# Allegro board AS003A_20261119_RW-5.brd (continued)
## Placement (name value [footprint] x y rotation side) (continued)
NOREF#208  -  []  327.06 232.39 0 top
NOREF#209  -  []  289.38 211.71 90 top
NOREF#210  -  []  355.47 246.3 90 top
NOREF#211  -  []  282.75 189.55 0 top
NOREF#212  -  []  266.93 277.4 90 top
NOREF#213  -  []  295.78 216.51 0 top
NOREF#214  -  []  296.03 211.93 90 top
NOREF#215  -  []  288.58 217.31 90 top
NOREF#216  -  []  295.78 214.91 90 top
NOREF#217  -  []  254.59 208.91 0 top
NOREF#218  -  []  298.43 215.93 90 top
NOREF#219  -  []  312.79 276.59 0 top
NOREF#220  -  []  298.13 277.21 0 top
NOREF#221  -  []  73.08 198.04 90 top
NOREF#222  -  []  282.98 208.51 0 top
NOREF#223  -  []  238.25 277.7 90 top
NOREF#224  -  []  313.37 277.4 90 top
NOREF#225  -  []  306.49 215.7 90 top
NOREF#226  -  []  290.98 214.91 0 top
NOREF#227  -  []  343.76 238.65 0 top
NOREF#228  -  []  296.58 218.91 90 top
NOREF#229  -  []  292.33 247.22 0 top
NOREF#230  -  []  328.93 276.31 90 top
NOREF#231  -  []  293.38 217.31 90 top
NOREF#232  -  []  39.3 175.77 0 top
NOREF#233  -  []  288.58 214.11 0 top
NOREF#234  -  []  281.85 277.7 90 top
NOREF#235  -  []  297.85 277.7 0 top
NOREF#236  -  []  289.38 218.11 0 top
NOREF#237  -  []  296.83 217.53 90 top
NOREF#238  -  []  292.58 208.51 0 top
NOREF#239  -  []  253.82 277.4 90 top
NOREF#240  -  []  293.38 209.31 0 top
NOREF#241  -  []  292.35 251.77 0 top
NOREF#242  -  []  275.17 219.77 90 top
NOREF#243  -  []  282.17 277.4 90 top
NOREF#244  -  []  56.28 217.19 90 top
NOREF#245  -  []  292.03 211.13 90 top
NOREF#246  -  []  283.78 207.71 0 top
NOREF#247  -  []  288.58 217.31 0 top
NOREF#248  -  []  284.83 210.33 90 top
NOREF#249  -  []  292.58 213.31 90 top
NOREF#250  -  []  306.49 212.15 90 top
NOREF#251  -  []  343.22 225.85 0 top
NOREF#252  -  []  280.08 250.87 0 top
NOREF#253  -  []  54.49 178.75 90 top
NOREF#254  -  []  268.41 276.01 0 top
NOREF#255  -  []  364.36 226.82 90 top
NOREF#256  -  []  297.63 210.33 90 top
NOREF#257  -  []  55.48 174.78 90 top
NOREF#258  -  []  284.3 277.4 90 top
NOREF#259  -  []  286.98 209.31 0 top
NOREF#260  -  []  297.63 213.53 90 top
NOREF#261  -  []  297.57 177.1 90 top
NOREF#262  -  []  166.64 181.61 0 top
NOREF#263  -  []  293.63 207.93 90 top
NOREF#264  -  []  54.49 203.06 0 top
NOREF#265  -  []  56 218.47 0 top
NOREF#266  -  []  44.57 154.4 0 top
NOREF#267  -  []  286.18 208.51 0 top
NOREF#268  -  []  354.12 225.85 90 top
NOREF#269  -  []  284.58 213.31 90 top
NOREF#270  -  []  355.88 241.56 90 top
NOREF#271  -  []  297.63 207.13 90 top
NOREF#272  -  []  294.18 216.51 90 top
NOREF#273  -  []  330.5 196.49 0 top
NOREF#274  -  []  303.28 179.07 90 top
NOREF#275  -  []  354.57 229.03 0 top
NOREF#276  -  []  290.18 209.31 0 top
NOREF#277  -  []  347.47 240.77 90 top
NOREF#278  -  []  349.27 247.73 0 top
NOREF#279  -  []  313.69 277.7 90 top
NOREF#280  -  []  283.78 210.91 90 top
NOREF#281  -  []  260.1 196.6 0 top
NOREF#282  -  []  345.26 277.4 90 top
NOREF#283  -  []  344.47 277.38 90 top
NOREF#284  -  []  309.79 201.48 90 top
NOREF#285  -  []  39.3 214.88 90 top
NOREF#286  -  []  180.76 158.43 0 top
NOREF#287  -  []  284.58 211.71 0 top
NOREF#288  -  []  331.47 283.21 90 top
NOREF#289  -  []  283.78 215.71 90 top
NOREF#290  -  []  297.38 210.11 0 top
NOREF#291  -  []  282.98 218.11 90 top
NOREF#292  -  []  282.98 214.91 90 top
NOREF#293  -  []  321.56 248.44 0 top
NOREF#294  -  []  328.61 277.4 90 top
NOREF#295  -  []  281.52 276.01 0 top
NOREF#296  -  []  292.83 216.73 90 top
NOREF#297  -  []  56.28 199.07 90 top
NOREF#298  -  []  282.31 277.38 0 top
NOREF#299  -  []  346.86 236.37 90 top
NOREF#300  -  []  39.3 174.07 90 top
NOREF#301  -  []  281.52 278.6 0 top
NOREF#302  -  []  275.17 209.1 90 top
NOREF#303  -  []  120.83 125.63 90 top
NOREF#304  -  []  296.16 177.75 0 top
NOREF#305  -  []  360.49 237.54 0 top
NOREF#306  -  []  296.83 220.73 90 top
NOREF#307  -  []  344.47 276.59 90 top
NOREF#308  -  []  283.65 251.38 0 top
NOREF#309  -  []  294.18 216.51 0 top
NOREF#310  -  []  311.15 283.21 0 top
NOREF#311  -  []  298.18 218.91 90 top
NOREF#312  -  []  297.63 208.73 90 top
NOREF#313  -  []  294.98 209.31 90 top
NOREF#314  -  []  250.19 283.21 0 top
NOREF#315  -  []  298.18 217.31 0 top
NOREF#316  -  []  284.03 207.93 90 top
NOREF#317  -  []  337.75 227.88 90 top
NOREF#318  -  []  293.94 185.5 0 top
NOREF#319  -  []  294.43 208.73 90 top
NOREF#320  -  []  296.58 217.31 0 top
NOREF#321  -  []  354.56 241.12 0 top
NOREF#322  -  []  268.73 276.31 90 top
NOREF#323  -  []  309.63 184.4 90 top
NOREF#324  -  []  275.17 225.1 90 top
NOREF#325  -  []  252.73 277.7 90 top
NOREF#326  -  []  288.03 215.13 90 top
NOREF#327  -  []  55.48 215.59 0 top
NOREF#328  -  []  61.66 214.21 0 top
NOREF#329  -  []  283.45 251.12 90 top
NOREF#330  -  []  278.43 226.23 90 top
NOREF#331  -  []  278.43 227.03 0 top
NOREF#332  -  []  267.65 277.4 0 top
NOREF#333  -  []  283.65 278.6 0 top
NOREF#334  -  []  306.49 219.26 90 top
NOREF#335  -  []  293.38 207.71 0 top
NOREF#336  -  []  252.41 277.4 0 top
NOREF#337  -  []  252.13 276.91 0 top
NOREF#338  -  []  298.89 276.01 0 top
NOREF#339  -  []  98.83 292.88 90 top
NOREF#340  -  []  287.71 222.43 0 top
NOREF#341  -  []  296.76 276.01 0 top
NOREF#342  -  []  354.83 238.87 90 top
NOREF#343  -  []  267.65 277.4 90 top
NOREF#344  -  []  290.18 212.51 90 top
NOREF#345  -  []  362.14 242.14 0 top
NOREF#346  -  []  321.29 245.75 0 top
NOREF#347  -  []  287.78 206.91 0 top
NOREF#348  -  []  295.23 212.73 90 top
NOREF#349  -  []  285.38 214.11 0 top
NOREF#350  -  []  290.13 198.97 0 top
NOREF#351  -  []  329.69 277.7 90 top
NOREF#352  -  []  285.23 251.38 90 top
NOREF#353  -  []  299.54 277.4 90 top
NOREF#354  -  []  291.78 209.31 0 top
NOREF#355  -  []  285.75 283.21 90 top
NOREF#356  -  []  296.83 214.33 90 top
NOREF#357  -  []  39.75 217.68 90 top
NOREF#358  -  []  73.53 200.07 90 top
NOREF#359  -  []  309.89 217.48 90 top
NOREF#360  -  []  263.65 172.97 0 top
NOREF#361  -  []  282.98 214.91 0 top
NOREF#362  -  []  294.94 189.55 0 top
NOREF#363  -  []  67.71 201.67 0 top
NOREF#364  -  []  306.49 208.59 90 top
NOREF#365  -  []  288.03 221.53 90 top
NOREF#366  -  []  270.51 182.63 0 top
NOREF#367  -  []  56.28 200.05 90 top
NOREF#368  -  []  337.48 247.4 0 top
NOREF#369  -  []  297.41 277.4 90 top
NOREF#370  -  []  297.38 213.31 90 top
NOREF#371  -  []  73.08 174.37 90 top
NOREF#372  -  []  287.23 214.33 90 top
NOREF#373  -  []  297.24 195.57 0 top
NOREF#374  -  []  55.48 198.45 90 top
NOREF#375  -  []  325.14 217.5 0 top
NOREF#376  -  []  287.78 216.51 90 top
NOREF#377  -  []  288.58 209.31 0 top
NOREF#378  -  []  320.74 200.23 0 top
NOREF#379  -  []  287.78 213.31 90 top
NOREF#380  -  []  268.41 276.01 90 top
NOREF#381  -  []  67.71 178 0 top
NOREF#382  -  []  72.69 197.67 90 top
NOREF#383  -  []  291.78 212.51 90 top
NOREF#384  -  []  39.3 199.43 0 top
NOREF#385  -  []  290.98 208.51 0 top
NOREF#386  -  []  56.28 175.41 0 top
NOREF#387  -  []  72.69 156.86 0 top
NOREF#388  -  []  275.17 201.99 90 top
NOREF#389  -  []  290.43 209.53 90 top
NOREF#390  -  []  297.94 165.48 0 top
NOREF#391  -  []  287.78 214.91 0 top
NOREF#392  -  []  356.45 217.99 90 top
NOREF#393  -  []  348.07 234.96 0 top
NOREF#394  -  []  289.38 206.91 0 top
NOREF#395  -  []  290.98 211.71 0 top
NOREF#396  -  []  296.03 210.33 90 top
NOREF#397  -  []  292.58 206.91 0 top
NOREF#398  -  []  298.18 220.51 90 top
NOREF#399  -  []  235.8 278.6 0 top
NOREF#400  -  []  72.43 216.67 0 top
NOREF#401  -  []  371.64 240.17 0 top
NOREF#402  -  []  298.43 209.53 90 top
NOREF#403  -  []  267.65 277.21 0 top
NOREF#404  -  []  315.83 239.63 90 top
NOREF#405  -  []  55.48 157.64 0 top
NOREF#406  -  []  67.71 160.86 0 top
NOREF#407  -  []  271.77 207.32 90 top
NOREF#408  -  []  39.75 176.87 90 top
NOREF#409  -  []  298.43 212.73 90 top
NOREF#410  -  []  321.82 232.92 90 top
NOREF#411  -  []  328.33 277.7 0 top
NOREF#412  -  []  303.23 202.23 90 top
NOREF#413  -  []  344.87 230.45 0 top
NOREF#414  -  []  343.22 225.85 0 top
NOREF#415  -  []  297.63 216.73 90 top
NOREF#416  -  []  391.67 256.29 0 top
NOREF#417  -  []  291.78 212.51 0 top
NOREF#418  -  []  295.91 206.78 90 top
NOREF#419  -  []  237.17 277.21 0 top
NOREF#420  -  []  290.13 195.57 0 top
NOREF#421  -  []  65.7 227.81 0 top
NOREF#422  -  []  336.96 244.53 90 top
NOREF#423  -  []  286.18 211.71 90 top
NOREF#424  -  []  298.43 206.33 90 top
NOREF#425  -  []  61.66 173.4 0 top
NOREF#426  -  []  291.23 207.13 90 top
NOREF#427  -  []  72.69 197.67 0 top
NOREF#428  -  []  267.58 229.66 0 top
NOREF#429  -  []  333.38 187.96 90 top
NOREF#430  -  []  330.44 198.81 0 top
NOREF#431  -  []  292.05 183.93 0 top
NOREF#432  -  []  286.18 218.11 0 top
NOREF#433  -  []  252.41 277.21 0 top
NOREF#434  -  []  278.43 227.03 0 top
NOREF#435  -  []  336.84 231.21 0 top
NOREF#436  -  []  371.9 238.4 0 top
NOREF#437  -  []  320.74 200.23 0 top
NOREF#438  -  []  295.73 241.62 0 top
NOREF#439  -  []  265.43 283.21 0 top
NOREF#440  -  []  98.13 293.15 90 top
NOREF#441  -  []  294.18 208.51 0 top
NOREF#442  -  []  284.03 211.13 90 top
NOREF#443  -  []  316.23 283.21 90 top
NOREF#444  -  []  272.6 181.44 0 top
NOREF#445  -  []  343.57 277.7 0 top
NOREF#446  -  []  255.27 266.32 90 top
NOREF#447  -  []  284.58 206.91 0 top
NOREF#448  -  []  282.98 219.71 90 top
NOREF#449  -  []  252.13 277.7 0 top
NOREF#450  -  []  284.83 216.73 90 top
NOREF#451  -  []  263.84 208.36 0 top
NOREF#452  -  []  289.35 182.3 90 top
NOREF#453  -  []  298.18 217.31 90 top
NOREF#454  -  []  271.77 214.43 90 top
NOREF#455  -  []  331.34 198.81 90 top
NOREF#456  -  []  284.58 206.91 90 top
NOREF#457  -  []  283.78 220.51 90 top
NOREF#458  -  []  344.87 247.73 0 top
NOREF#459  -  []  294.98 217.31 0 top
NOREF#460  -  []  56.28 199.07 0 top
NOREF#461  -  []  293.38 212.51 90 top
NOREF#462  -  []  294.18 210.11 0 top
NOREF#463  -  []  298.18 212.51 90 top
NOREF#464  -  []  395.73 229.36 90 top
NOREF#465  -  []  320.74 217.5 0 top
NOREF#466  -  []  289.38 206.91 90 top
NOREF#467  -  []  120.83 303.63 0 top
NOREF#468  -  []  292.58 218.11 0 top
NOREF#469  -  []  61.66 214.21 0 top
NOREF#470  -  []  294.98 212.51 90 top
NOREF#471  -  []  236.13 277.7 90 top
NOREF#472  -  []  347.15 241.07 90 top
NOREF#473  -  []  326.51 241.52 0 top
NOREF#474  -  []  271.77 216.21 90 top
NOREF#475  -  []  321.5 243.5 90 top
NOREF#476  -  []  41.66 199.56 90 top
NOREF#477  -  []  290.98 218.11 90 top
NOREF#478  -  []  295.46 195.57 0 top
NOREF#479  -  []  268.27 277.38 90 top
NOREF#480  -  []  275.17 214.43 90 top
NOREF#481  -  []  294.18 219.71 90 top
NOREF#482  -  []  284.83 215.13 90 top
NOREF#483  -  []  290.18 209.31 90 top
NOREF#484  -  []  289.38 214.91 0 top
NOREF#485  -  []  294.43 216.73 90 top
NOREF#486  -  []  296.03 215.13 90 top
NOREF#487  -  []  288.58 209.31 90 top
NOREF#488  -  []  290.18 215.71 0 top
NOREF#489  -  []  421.83 285.33 0 top
NOREF#490  -  []  298.18 214.11 0 top
NOREF#491  -  []  300.54 174.21 0 top
NOREF#492  -  []  287.78 210.11 90 top
NOREF#493  -  []  265.83 189.63 90 top
NOREF#494  -  []  297.63 219.93 90 top
NOREF#495  -  []  330.89 196.85 90 top
NOREF#496  -  []  267.37 276.91 0 top
NOREF#497  -  []  237.79 277.38 90 top
NOREF#498  -  []  283.78 209.31 90 top
NOREF#499  -  []  300.79 198.97 0 top
NOREF#500  -  []  39.3 158.62 0 top
NOREF#501  -  []  298.13 277.4 0 top
NOREF#502  -  []  296.14 185.5 0 top
NOREF#503  -  []  313.99 277.38 90 top
NOREF#504  -  []  329.14 240.86 0 top
NOREF#505  -  []  346.83 233.92 0 top
NOREF#506  -  []  251.04 276.01 90 top
NOREF#507  -  []  300.99 283.21 90 top
NOREF#508  -  []  266.28 276.01 0 top
NOREF#509  -  []  296.83 211.13 90 top
NOREF#510  -  []  297.38 206.91 0 top
NOREF#511  -  []  253.49 277.7 90 top
NOREF#512  -  []  354.37 245.75 0 top
NOREF#513  -  []  326.51 224.25 0 top
NOREF#514  -  []  73.7 225.98 90 top
NOREF#515  -  []  278.43 202.23 90 top
NOREF#516  -  []  288.03 210.33 90 top
NOREF#517  -  []  293.38 214.11 90 top
NOREF#518  -  []  251.04 278.6 0 top
NOREF#519  -  []  44.57 195.21 0 top
NOREF#520  -  []  291.56 221.23 90 top
NOREF#521  -  []  295.78 208.51 0 top
NOREF#522  -  []  298.18 207.71 90 top
NOREF#523  -  []  290.98 214.91 90 top
NOREF#524  -  []  284.58 208.51 0 top
NOREF#525  -  []  296.76 278.6 0 top
NOREF#526  -  []  287.78 211.71 0 top
NOREF#527  -  []  285.38 212.51 0 top
NOREF#528  -  []  265.83 245.63 90 top
NOREF#529  -  []  296.58 220.51 0 top
NOREF#530  -  []  295.78 211.71 0 top
NOREF#531  -  []  322.34 229.59 90 top
NOREF#532  -  []  296.58 214.11 90 top
NOREF#533  -  []  273.33 226.91 0 top
NOREF#534  -  []  288.58 218.91 90 top
NOREF#535  -  []  354.12 243.13 90 top
NOREF#536  -  []  354.57 246.3 0 top
NOREF#537  -  []  298.43 217.53 90 top
NOREF#538  -  []  291.78 218.91 0 top
NOREF#539  -  []  330.89 198.91 90 top
NOREF#540  -  []  276.41 181.44 0 top
NOREF#541  -  []  295.78 210.11 0 top
NOREF#542  -  []  290.13 247.22 0 top
NOREF#543  -  []  251.69 277.4 90 top
NOREF#544  -  []  281.85 276.31 90 top
NOREF#545  -  []  250.19 266.32 0 top
NOREF#546  -  []  292.83 213.53 90 top
NOREF#547  -  []  286.98 212.51 90 top
NOREF#548  -  []  285.38 209.31 90 top
NOREF#549  -  []  282.98 206.91 0 top
NOREF#550  -  []  265.68 173.99 90 top
NOREF#551  -  []  297.09 276.31 90 top
NOREF#552  -  []  286.18 219.71 0 top
NOREF#553  -  []  283.53 276.01 90 top
NOREF#554  -  []  297.38 211.71 90 top
NOREF#555  -  []  290.13 247.22 0 top
NOREF#556  -  []  372.74 240.72 90 top
NOREF#557  -  []  283.95 185.5 0 top
NOREF#558  -  []  271.61 200.46 90 top
NOREF#559  -  []  329.69 276.31 90 top
NOREF#560  -  []  298.18 209.31 0 top
NOREF#561  -  []  282.98 211.71 90 top
NOREF#562  -  []  295.78 213.31 90 top
NOREF#563  -  []  290.43 214.33 90 top
NOREF#564  -  []  285.93 177.3 0 top
NOREF#565  -  []  288.58 210.91 0 top
NOREF#566  -  []  263.65 172.97 90 top
NOREF#567  -  []  286.43 208.73 90 top
NOREF#568  -  []  289.63 216.73 90 top
NOREF#569  -  []  285.38 212.51 90 top
NOREF#570  -  []  364.34 242.14 0 top
NOREF#571  -  []  286.98 215.71 90 top
NOREF#572  -  []  70.91 174.8 0 top
NOREF#573  -  []  283.23 216.73 90 top
NOREF#574  -  []  295.23 214.33 90 top
NOREF#575  -  []  297.55 276.59 0 top
NOREF#576  -  []  298.18 215.71 90 top
NOREF#577  -  []  284.83 207.13 90 top
NOREF#578  -  []  39.75 157.02 90 top
NOREF#579  -  []  344.61 276.01 0 top
NOREF#580  -  []  293.63 217.53 90 top
NOREF#581  -  []  288.03 208.73 90 top
NOREF#582  -  []  47.2 194.55 0 top
NOREF#583  -  []  72.43 199.52 0 top
NOREF#584  -  []  327.28 202.95 0 top
NOREF#585  -  []  73.53 159.26 90 top
NOREF#586  -  []  237.93 276.01 90 top
NOREF#587  -  []  291.78 217.31 0 top
NOREF#588  -  []  289.38 213.31 0 top
NOREF#589  -  []  312.65 277.4 90 top
NOREF#590  -  []  289.63 215.13 90 top
NOREF#591  -  []  290.91 222.43 0 top
NOREF#592  -  []  260.24 208.36 0 top
NOREF#593  -  []  337.75 246.13 90 top
NOREF#594  -  []  283.97 276.31 90 top
NOREF#595  -  []  327.24 278.6 0 top
NOREF#596  -  []  295.8 178.14 0 top
NOREF#597  -  []  73.08 200.17 90 top
NOREF#598  -  []  290.43 207.93 90 top
NOREF#599  -  []  72.63 217.21 0 top
NOREF#600  -  []  296.58 209.31 90 top
NOREF#601  -  []  287.23 215.93 90 top
NOREF#602  -  []  290.18 215.71 90 top
NOREF#603  -  []  283.78 214.11 90 top
NOREF#604  -  []  341.63 266.32 0 top
NOREF#605  -  []  73.08 176.5 90 top
NOREF#606  -  []  253.69 207.68 90 top
NOREF#607  -  []  437.15 0 90 top
NOREF#608  -  []  283.65 276.01 90 top
NOREF#609  -  []  292.35 183.61 0 top
NOREF#610  -  []  319.09 212.9 0 top
NOREF#611  -  []  283.61 178.14 0 top
NOREF#612  -  []  253.05 276.01 90 top
NOREF#613  -  []  287.23 217.53 90 top
NOREF#614  -  []  303.11 197.13 90 top
NOREF#615  -  []  282.31 276.59 0 top
NOREF#616  -  []  321.56 231.17 0 top
NOREF#617  -  []  327.06 249.66 0 top
NOREF#618  -  []  331.34 216.08 90 top
NOREF#619  -  []  289.63 211.93 90 top
NOREF#620  -  []  335.41 188.98 90 top
NOREF#621  -  []  371.39 237.54 90 top
NOREF#622  -  []  296.58 209.31 0 top
NOREF#623  -  []  270.51 266.32 90 top
NOREF#624  -  []  336.84 247.84 90 top
NOREF#625  -  []  287.78 210.11 0 top
NOREF#626  -  []  293.63 212.73 90 top
NOREF#627  -  []  280.67 266.32 0 top
NOREF#628  -  []  296.58 207.71 90 top
NOREF#629  -  []  253.03 276.59 90 top
NOREF#630  -  []  332.36 202.95 90 top
NOREF#631  -  []  312 276.01 0 top
NOREF#632  -  []  73.53 217.21 90 top
NOREF#633  -  []  294.98 210.91 0 top
NOREF#634  -  []  393.7 230.38 90 top
NOREF#635  -  []  294.43 218.33 90 top
NOREF#636  -  []  163.61 158.43 90 top
NOREF#637  -  []  56.28 158.26 0 top
NOREF#638  -  []  291.9 198.97 0 top
NOREF#639  -  []  306.49 205.04 90 top
NOREF#640  -  []  283.78 215.71 0 top
NOREF#641  -  []  294.18 211.71 90 top
NOREF#642  -  []  344.81 218.95 0 top
NOREF#643  -  []  289.38 214.91 90 top
NOREF#644  -  []  65.51 218.81 0 top
NOREF#645  -  []  282.98 213.31 0 top
NOREF#646  -  []  286.57 198.97 0 top
NOREF#647  -  []  254.59 208.91 0 top
NOREF#648  -  []  328.03 276.59 0 top
NOREF#649  -  []  293.63 211.13 90 top
NOREF#650  -  []  288.83 219.13 90 top
NOREF#651  -  []  283.21 276.31 90 top
NOREF#652  -  []  294.98 218.91 0 top
NOREF#653  -  []  298.22 177.75 0 top
NOREF#654  -  []  253.24 204.88 90 top
NOREF#655  -  []  39.36 218.89 0 top
NOREF#656  -  []  296.03 213.53 90 top
NOREF#657  -  []  350.45 236.76 90 top
NOREF#658  -  []  294.98 207.71 0 top
NOREF#659  -  []  352.47 227.25 90 top
NOREF#660  -  []  40.14 159.36 90 top
NOREF#661  -  []  268.29 276.01 90 top
NOREF#662  -  []  292.95 185.53 90 top
NOREF#663  -  []  294.98 215.71 0 top
NOREF#664  -  []  287.78 208.51 90 top
NOREF#665  -  []  296.76 276.01 90 top
NOREF#666  -  []  298.18 214.11 90 top
NOREF#667  -  []  282.98 216.51 0 top
NOREF#668  -  []  297.38 211.71 0 top
NOREF#669  -  []  275.8 191.38 90 top
NOREF#670  -  []  283.23 211.93 90 top
NOREF#671  -  []  39.1 176.32 0 top
NOREF#672  -  []  298.18 222.11 90 top
NOREF#673  -  []  234.95 283.21 0 top
NOREF#674  -  []  297.94 165.48 90 top
NOREF#675  -  []  36.89 225.87 0 top
NOREF#676  -  []  266.06 166.12 90 top
NOREF#677  -  []  294.98 217.31 90 top
NOREF#678  -  []  337.75 245.15 90 top
NOREF#679  -  []  283.23 210.33 90 top
NOREF#680  -  []  319.09 212.9 0 top
NOREF#681  -  []  327.24 276.01 0 top
NOREF#682  -  []  284.03 219.13 90 top
NOREF#683  -  []  326.39 283.21 0 top
NOREF#684  -  []  251.04 276.01 0 top
NOREF#685  -  []  291.78 217.31 90 top
NOREF#686  -  []  290.18 207.71 90 top
NOREF#687  -  []  291.78 209.31 90 top
NOREF#688  -  []  286.98 207.71 0 top
NOREF#689  -  []  255.84 208.36 0 top
NOREF#690  -  []  286.43 216.73 90 top
NOREF#691  -  []  281.24 198.97 0 top
NOREF#692  -  []  120.83 135.63 0 top
NOREF#693  -  []  297.63 211.93 90 top
NOREF#694  -  []  284.58 216.51 90 top
NOREF#695  -  []  293.63 209.53 90 top
NOREF#696  -  []  288.58 210.91 90 top
NOREF#697  -  []  128.85 125.63 90 top
NOREF#698  -  []  56.28 216.22 0 top
NOREF#699  -  []  284.58 208.51 90 top
NOREF#700  -  []  292.58 218.11 90 top
NOREF#701  -  []  285.63 215.93 90 top
NOREF#702  -  []  309.89 226.37 90 top
NOREF#703  -  []  309.89 222.82 90 top
NOREF#704  -  []  291.78 207.71 0 top
NOREF#705  -  []  344.87 247.73 0 top
NOREF#706  -  []  294.98 214.11 0 top
NOREF#707  -  []  372.29 240.82 90 top
NOREF#708  -  []  63.31 160.86 0 top
NOREF#709  -  []  266.61 277.7 90 top
NOREF#710  -  []  253.17 278.6 0 top
NOREF#711  -  []  339.43 244.85 90 top
NOREF#712  -  []  294.53 247.22 0 top
NOREF#713  -  []  70.91 198.47 90 top
NOREF#714  -  []  283.51 277.38 90 top
NOREF#715  -  []  287.23 207.93 90 top
NOREF#716  -  []  252.41 277.4 90 top
NOREF#717  -  []  236.89 277.7 0 top
NOREF#718  -  []  337.75 245.15 0 top
NOREF#719  -  []  268.27 276.59 90 top
NOREF#720  -  []  312.33 277.7 90 top
NOREF#721  -  []  354.68 241.56 0 top
NOREF#722  -  []  282.89 277.21 0 top
NOREF#723  -  []  163.07 158.23 90 top
NOREF#724  -  []  298.18 212.51 0 top
NOREF#725  -  []  286.98 215.71 0 top
NOREF#726  -  []  283.78 207.71 90 top
NOREF#727  -  []  292.58 214.91 0 top
NOREF#728  -  []  240.03 266.32 90 top
NOREF#729  -  []  321.94 229.95 90 top
NOREF#730  -  []  298.89 278.6 0 top
NOREF#731  -  []  287.23 209.53 90 top
NOREF#732  -  []  283.65 276.01 0 top
NOREF#733  -  []  294.18 219.71 0 top
NOREF#734  -  []  293.95 251.32 90 top
NOREF#735  -  []  354.37 228.48 0 top
NOREF#736  -  []  344.93 277.7 90 top
NOREF#737  -  []  282.98 211.71 0 top
NOREF#738  -  []  284.58 210.11 90 top
NOREF#739  -  []  265.83 239.63 0 top
NOREF#740  -  []  298.18 206.11 0 top
NOREF#741  -  []  314.45 277.7 90 top
NOREF#742  -  []  298.45 276.31 90 top
NOREF#743  -  []  41.66 216.71 90 top
NOREF#744  -  []  327.24 276.01 90 top
NOREF#745  -  []  299.02 195.57 0 top
NOREF#746  -  []  347.07 230.45 0 top
NOREF#747  -  []  67.71 218.81 0 top
NOREF#748  -  []  291.23 221.53 90 top
NOREF#749  -  []  298.18 218.91 0 top
NOREF#750  -  []  291.23 208.73 90 top
NOREF#751  -  []  352.47 227.25 0 top
NOREF#752  -  []  346.71 283.21 90 top
NOREF#753  -  []  258.04 208.36 0 top
NOREF#754  -  []  289.38 216.51 0 top
NOREF#755  -  []  290.98 206.91 0 top
NOREF#756  -  []  271.77 203.77 90 top
NOREF#757  -  []  288.58 207.71 0 top
NOREF#758  -  []  313.35 226.37 90 top
NOREF#759  -  []  294.94 189.55 0 top
NOREF#760  -  []  39.3 216.58 0 top
NOREF#761  -  []  284.58 214.91 0 top
NOREF#762  -  []  265.43 266.32 0 top
NOREF#763  -  []  295.78 210.11 90 top
NOREF#764  -  []  346.83 233.92 90 top
NOREF#765  -  []  354.83 238.87 0 top
NOREF#766  -  []  72.69 174.01 0 top
NOREF#767  -  []  290.98 216.51 0 top
NOREF#768  -  []  344.61 276.01 90 top
NOREF#769  -  []  309.89 210.37 90 top
NOREF#770  -  []  266.53 217.99 90 top
NOREF#771  -  []  251.37 277.7 90 top
NOREF#772  -  []  266.28 276.01 90 top
NOREF#773  -  []  63.31 160.86 0 top
NOREF#774  -  []  348.37 235.28 0 top
NOREF#775  -  []  297.85 276.91 0 top
NOREF#776  -  []  295.78 216.51 90 top
NOREF#777  -  []  297.63 215.13 90 top
NOREF#778  -  []  73.53 176.4 90 top
NOREF#779  -  []  328.34 214.3 90 top
NOREF#780  -  []  298.18 222.11 0 top
NOREF#781  -  []  281.21 252.22 0 top
NOREF#782  -  []  308.33 197.13 90 top
NOREF#783  -  []  337.75 228.85 90 top
NOREF#784  -  []  288.83 211.13 90 top
NOREF#785  -  []  288.83 207.93 90 top
NOREF#786  -  []  39.75 159.72 90 top
NOREF#787  -  []  347.07 247.73 0 top
NOREF#788  -  []  343.85 277.4 90 top
NOREF#789  -  []  286.43 215.13 90 top
NOREF#790  -  []  267.97 277.7 90 top
NOREF#791  -  []  299.02 198.97 0 top
NOREF#792  -  []  54.49 220.2 0 top
NOREF#793  -  []  364.36 226.82 0 top
NOREF#794  -  []  39.3 197.74 90 top
NOREF#795  -  []  290.18 214.11 0 top
NOREF#796  -  []  286.03 177.75 0 top
NOREF#797  -  []  73.08 215.18 90 top
NOREF#798  -  []  278.43 202.23 0 top
NOREF#799  -  []  288.35 198.97 0 top
NOREF#800  -  []  295.23 211.13 90 top
NOREF#801  -  []  236.89 276.91 0 top
NOREF#802  -  []  279.46 195.67 0 top
NOREF#803  -  []  284.83 221.53 90 top
NOREF#804  -  []  309.89 212.15 90 top
NOREF#805  -  []  288.83 215.93 90 top
NOREF#806  -  []  49.58 197.22 90 top
NOREF#807  -  []  283.01 198.97 0 top
NOREF#808  -  []  297.38 213.31 0 top
NOREF#809  -  []  319.09 195.63 0 top
NOREF#810  -  []  341.63 283.21 0 top
NOREF#811  -  []  348.49 240.77 90 top
NOREF#812  -  []  298.89 276.01 90 top
NOREF#813  -  []  168.24 190.05 90 top
NOREF#814  -  []  297.38 210.11 90 top
NOREF#815  -  []  293.38 214.11 0 top
NOREF#816  -  []  325.14 200.23 0 top
NOREF#817  -  []  266.53 216.21 90 top
NOREF#818  -  []  295.78 214.91 0 top
NOREF#819  -  []  305.37 195.67 0 top
NOREF#820  -  []  253.24 206.58 0 top
NOREF#821  -  []  286.18 219.71 90 top
NOREF#822  -  []  265.83 189.63 0 top
NOREF#823  -  []  298.77 276.01 90 top
NOREF#824  -  []  283.78 217.31 90 top
NOREF#825  -  []  286.43 213.53 90 top
NOREF#826  -  []  166.64 190.5 0 top
NOREF#827  -  []  294.43 215.13 90 top
NOREF#828  -  []  56.28 158.26 90 top
NOREF#829  -  []  298.18 207.71 0 top
NOREF#830  -  []  331.52 226.26 90 top
NOREF#831  -  []  339.43 227.58 90 top
NOREF#832  -  []  354.63 226.71 90 top
NOREF#833  -  []  289.38 213.31 90 top
NOREF#834  -  []  289.63 208.73 90 top
NOREF#835  -  []  285.23 250.87 0 top
NOREF#836  -  []  291.78 210.91 90 top
NOREF#837  -  []  291.13 250.87 0 top
NOREF#838  -  []  354.63 243.98 0 top
NOREF#839  -  []  323.6 245.87 90 top
NOREF#840  -  []  321.94 226.33 90 top
NOREF#841  -  []  72.63 176.4 0 top
NOREF#842  -  []  294.98 207.71 90 top
NOREF#843  -  []  293.38 218.91 0 top
NOREF#844  -  []  328.61 277.4 0 top
NOREF#845  -  []  285.38 209.31 0 top
NOREF#846  -  []  291.9 195.57 0 top
NOREF#847  -  []  371.9 238.4 90 top
NOREF#848  -  []  293.38 209.31 90 top
NOREF#849  -  []  292.83 208.73 90 top
NOREF#850  -  []  352.47 244.53 0 top
NOREF#851  -  []  306.49 213.93 90 top
NOREF#852  -  []  298.18 220.51 0 top
NOREF#853  -  []  292.83 211.93 90 top
NOREF#854  -  []  362.14 242.14 0 top
NOREF#855  -  []  327.7 194.11 90 top
NOREF#856  -  []  348.17 241.07 90 top
NOREF#857  -  []  291.23 215.13 90 top
NOREF#858  -  []  309.89 206.81 90 top
NOREF#859  -  []  288.03 207.13 90 top
NOREF#860  -  []  253.03 277.38 90 top
NOREF#861  -  []  288.83 217.53 90 top
NOREF#862  -  []  290.18 218.91 90 top
NOREF#863  -  []  292.05 183.29 90 top
NOREF#864  -  []  293.68 195.57 0 top
NOREF#865  -  []  327.89 277.4 90 top
NOREF#866  -  []  73.08 157.23 90 top
NOREF#867  -  []  292.03 207.93 90 top
NOREF#868  -  []  319.66 182.88 0 top
NOREF#869  -  []  311.15 266.32 0 top
NOREF#870  -  []  284.83 218.33 90 top
NOREF#871  -  []  292.35 171.7 0 top
NOREF#872  -  []  284.68 249.22 0 top
NOREF#873  -  []  236.45 277.4 90 top
NOREF#874  -  []  331.47 266.32 90 top
NOREF#875  -  []  282.89 277.4 90 top
NOREF#876  -  []  344.93 276.31 90 top
NOREF#877  -  []  271.77 209.1 90 top
NOREF#878  -  []  343.22 243.13 0 top
NOREF#879  -  []  70.91 198.47 0 top
NOREF#880  -  []  267.58 199.6 0 top
NOREF#881  -  []  72.63 159.26 0 top
NOREF#882  -  []  287.23 219.13 90 top
NOREF#883  -  []  285.38 210.91 90 top
NOREF#884  -  []  171.87 137.47 90 top
NOREF#885  -  []  342.48 276.01 90 top
NOREF#886  -  []  63.31 218.81 0 top
NOREF#887  -  []  343.57 276.91 0 top
NOREF#888  -  []  286.18 216.51 0 top
NOREF#889  -  []  296.58 210.91 0 top
NOREF#890  -  []  292.58 210.11 90 top
NOREF#891  -  []  297.38 221.31 0 top
NOREF#892  -  []  180.76 158.43 90 top
NOREF#893  -  []  295.91 207.28 0 top
NOREF#894  -  []  255.84 208.36 0 top
NOREF#895  -  []  343.13 277.4 90 top
NOREF#896  -  []  290.98 210.11 0 top
NOREF#897  -  []  54.79 202.74 0 top
NOREF#898  -  []  54.49 161.6 90 top
NOREF#899  -  []  63.31 178 0 top
NOREF#900  -  []  295.23 217.53 90 top
NOREF#901  -  []  268.41 278.6 0 top
NOREF#902  -  []  356.51 238.57 90 top
NOREF#903  -  []  286.98 214.11 90 top
NOREF#904  -  []  72.56 214.21 90 top
NOREF#905  -  []  236.13 276.31 90 top
NOREF#906  -  []  330.5 213.76 90 top
NOREF#907  -  []  296.83 215.93 90 top
NOREF#908  -  []  286.18 213.31 0 top
NOREF#909  -  []  312.79 277.38 0 top
NOREF#910  -  []  286.98 212.51 0 top
NOREF#911  -  []  283.97 177.75 0 top
NOREF#912  -  []  350.13 236.46 90 top
NOREF#913  -  []  294.98 210.91 90 top
NOREF#914  -  []  345.56 239.92 0 top
NOREF#915  -  []  330.89 214.12 90 top
NOREF#916  -  []  346.16 239.32 0 top
NOREF#917  -  []  289.38 208.51 0 top
NOREF#918  -  []  297.09 277.7 90 top
NOREF#919  -  []  329.37 276.01 90 top
NOREF#920  -  []  271.77 205.54 90 top
NOREF#921  -  []  286.98 217.31 0 top
NOREF#922  -  []  286.98 209.31 90 top
NOREF#923  -  []  343.27 276.59 0 top
NOREF#924  -  []  355.02 246.41 90 top
NOREF#925  -  []  271.77 217.99 90 top
NOREF#926  -  []  344.17 276.31 90 top
NOREF#927  -  []  45.12 162.54 0 top
NOREF#928  -  []  295.78 213.31 0 top
NOREF#929  -  []  283.6 178.65 0 top
NOREF#930  -  []  353.84 235.08 90 top
NOREF#931  -  []  238.58 277.4 90 top
NOREF#932  -  []  320.74 217.5 0 top
NOREF#933  -  []  57.95 198.77 90 top
NOREF#934  -  []  282.91 251.32 90 top
NOREF#935  -  []  279.46 177.13 0 top
NOREF#936  -  []  288.83 214.33 90 top
NOREF#937  -  []  286.98 214.11 0 top
NOREF#938  -  []  306.49 224.59 90 top
NOREF#939  -  []  55.48 198.45 0 top
NOREF#940  -  []  236.59 276.59 0 top
NOREF#941  -  []  294.98 215.71 90 top
NOREF#942  -  []  40.14 217.31 90 top
NOREF#943  -  []  309.89 215.7 90 top
NOREF#944  -  []  286.98 217.31 90 top
NOREF#945  -  []  301.54 182.3 90 top
NOREF#946  -  []  287.23 212.73 90 top
NOREF#947  -  []  307.59 183.39 90 top
NOREF#948  -  []  297.38 214.91 0 top
NOREF#949  -  []  269.83 193.63 0 top
NOREF#950  -  []  282.98 216.51 90 top
NOREF#951  -  []  298.43 214.33 90 top
NOREF#952  -  []  286.15 185.5 0 top
NOREF#953  -  []  63.31 201.67 0 top
NOREF#954  -  []  39.1 217.13 0 top
NOREF#955  -  []  290.43 211.13 90 top
NOREF#956  -  []  284.83 219.93 90 top
NOREF#957  -  []  72.43 175.85 0 top
NOREF#958  -  []  292.58 214.91 90 top
NOREF#959  -  []  275.17 212.66 90 top
NOREF#960  -  []  277.68 195.67 0 top
NOREF#961  -  []  281.52 276.01 90 top
NOREF#962  -  []  44.57 212.36 0 top
NOREF#963  -  []  54.49 202.42 90 top
NOREF#964  -  []  309.89 203.26 90 top
NOREF#965  -  []  288.58 215.71 0 top
NOREF#966  -  []  54.79 161.93 0 top
NOREF#967  -  []  286.18 216.51 90 top
NOREF#968  -  []  287.78 216.51 0 top
NOREF#969  -  []  291.78 214.11 90 top
NOREF#970  -  []  298.43 219.13 90 top
NOREF#971  -  []  321.5 245.2 0 top
NOREF#972  -  []  286.43 210.33 90 top
NOREF#973  -  []  344.17 277.7 90 top
NOREF#974  -  []  293.63 214.33 90 top
NOREF#975  -  []  290.18 210.91 0 top
NOREF#976  -  []  47.2 153.74 0 top
NOREF#977  -  []  294.18 218.11 90 top
NOREF#978  -  []  321.5 226.23 90 top
NOREF#979  -  []  287.78 208.51 0 top
NOREF#980  -  []  296.58 210.91 90 top
NOREF#981  -  []  298.18 215.71 0 top
NOREF#982  -  []  234.95 266.32 0 top
NOREF#983  -  []  369.74 238.94 90 top
NOREF#984  -  []  285.73 207.03 0 top
NOREF#985  -  []  354.03 238.25 0 top
NOREF#986  -  []  297.73 244.02 90 top
NOREF#987  -  []  54.79 179.07 0 top
NOREF#988  -  []  284.03 212.73 90 top
NOREF#989  -  []  279.46 181.44 0 top
NOREF#990  -  []  286.57 195.57 0 top
NOREF#991  -  []  286.18 210.11 0 top
NOREF#992  -  []  322.94 217.5 0 top
NOREF#993  -  []  301.24 178.05 90 top
NOREF#994  -  []  286.18 213.31 90 top
NOREF#995  -  []  290.43 215.93 90 top
NOREF#996  -  []  299.21 276.31 90 top
NOREF#997  -  []  346.16 236.32 90 top
NOREF#998  -  []  298.34 185.5 0 top
NOREF#999  -  []  287.78 211.71 90 top
NOREF#1000  -  []  365.95 235.8 0 top
NOREF#1001  -  []  286.98 218.91 0 top
NOREF#1002  -  []  61.66 156.26 0 top
NOREF#1003  -  []  275.17 205.54 90 top
NOREF#1004  -  []  288.03 211.93 90 top
NOREF#1005  -  []  306.92 235.32 315 top
NOREF#1006  -  []  61.66 197.07 0 top
NOREF#1007  -  []  266.28 278.6 0 top
NOREF#1008  -  []  343.22 243.13 0 top
NOREF#1009  -  []  283.78 214.11 0 top
NOREF#1010  -  []  289.38 218.11 90 top
NOREF#1011  -  []  295.46 198.97 0 top
NOREF#1012  -  []  305.33 200.13 90 top
NOREF#1013  -  []  284.83 211.93 90 top
NOREF#1014  -  []  45.12 203.35 0 top
NOREF#1015  -  []  336.96 227.25 90 top
NOREF#1016  -  []  284.83 213.53 90 top
NOREF#1017  -  []  266.53 214.43 90 top
NOREF#1018  -  []  285.63 211.13 90 top
NOREF#1019  -  []  290.18 210.91 90 top
NOREF#1020  -  []  354.63 226.71 0 top
NOREF#1021  -  []  286.68 244.02 90 top
NOREF#1022  -  []  285.63 214.33 90 top
NOREF#1023  -  []  292.03 209.53 90 top
NOREF#1024  -  []  31.29 152.75 0 top
NOREF#1025  -  []  56.28 176.38 90 top
NOREF#1026  -  []  314.45 276.31 90 top
NOREF#1027  -  []  43.13 161.09 0 top
NOREF#1028  -  []  39.75 197.83 90 top
NOREF#1029  -  []  290.18 214.11 90 top
NOREF#1030  -  []  313.09 277.7 0 top
NOREF#1031  -  []  342.81 277.7 90 top
NOREF#1032  -  []  292.03 212.73 90 top
NOREF#1033  -  []  292.83 207.13 90 top
NOREF#1034  -  []  293.38 210.91 0 top
NOREF#1035  -  []  295.91 283.21 0 top
NOREF#1036  -  []  258.83 231.14 0 top
NOREF#1037  -  []  39.75 200.53 90 top
NOREF#1038  -  []  45.12 179.69 0 top
NOREF#1039  -  []  298.18 210.91 90 top
NOREF#1040  -  []  306.49 221.04 90 top
NOREF#1041  -  []  292.26 252.22 0 top
NOREF#1042  -  []  285.63 212.73 90 top
NOREF#1043  -  []  301.63 202.23 0 top
NOREF#1044  -  []  65.51 178 0 top
NOREF#1045  -  []  291.23 213.53 90 top
NOREF#1046  -  []  306.49 217.48 90 top
NOREF#1047  -  []  330.5 213.76 0 top
NOREF#1048  -  []  271.36 226.88 90 top
NOREF#1049  -  []  282.98 208.51 90 top
NOREF#1050  -  []  74.38 190.16 90 top
NOREF#1051  -  []  296.03 208.73 90 top
NOREF#1052  -  []  286.98 210.91 0 top
NOREF#1053  -  []  282.98 219.71 0 top
NOREF#1054  -  []  292.58 210.11 0 top
NOREF#1055  -  []  282.98 218.11 0 top
NOREF#1056  -  []  283.78 218.91 0 top
NOREF#1057  -  []  329.53 242.08 90 top
NOREF#1058  -  []  326.39 266.32 0 top
NOREF#1059  -  []  286.18 208.51 90 top
NOREF#1060  -  []  283.23 208.73 90 top
NOREF#1061  -  []  448.83 293.63 0 top
NOREF#1062  -  []  72.69 214.82 90 top
NOREF#1063  -  []  290.43 212.73 90 top
NOREF#1064  -  []  286.55 206.78 90 top
NOREF#1065  -  []  337.14 248.16 0 top
NOREF#1066  -  []  288.83 209.53 90 top
NOREF#1067  -  []  297.38 219.71 90 top
NOREF#1068  -  []  346.21 238.22 90 top
NOREF#1069  -  []  294.18 213.31 0 top
NOREF#1070  -  []  253.3 208.9 0 top
NOREF#1071  -  []  284.03 220.73 90 top
NOREF#1072  -  []  279.46 198.97 0 top
NOREF#1073  -  []  312.33 276.31 90 top
NOREF#1074  -  []  281.75 185.5 0 top
NOREF#1075  -  []  284.58 218.11 90 top
NOREF#1076  -  []  349.88 218.95 90 top
NOREF#1077  -  []  354.63 243.98 90 top
NOREF#1078  -  []  343.76 238.01 90 top
NOREF#1079  -  []  237.17 277.4 90 top
NOREF#1080  -  []  292.03 217.53 90 top
NOREF#1081  -  []  307.59 183.39 0 top
NOREF#1082  -  []  313.69 276.31 90 top
NOREF#1083  -  []  284.58 218.11 0 top
NOREF#1084  -  []  297.24 198.97 0 top
NOREF#1085  -  []  282.98 221.31 90 top
NOREF#1086  -  []  347.85 241.97 0 top
NOREF#1087  -  []  320.67 184.91 0 top
NOREF#1088  -  []  291.78 215.71 0 top
NOREF#1089  -  []  292.58 208.51 90 top
NOREF#1090  -  []  208.37 297.11 90 top
NOREF#1091  -  []  0 429.26 0 top
NOREF#1092  -  []  297.38 221.31 90 top
NOREF#1093  -  []  343.85 277.4 0 top
NOREF#1094  -  []  281.28 247.22 0 top
NOREF#1095  -  []  263.44 205.16 90 top
NOREF#1096  -  []  282.98 210.11 0 top
NOREF#1097  -  []  293.45 184.3 90 top
NOREF#1098  -  []  180.86 158.88 0 top
NOREF#1099  -  []  70.91 215.62 0 top
NOREF#1100  -  []  266.79 223.58 90 top
NOREF#1101  -  []  284.58 210.11 0 top
NOREF#1102  -  []  267.07 276.59 0 top
NOREF#1103  -  []  336.84 248.48 0 top
NOREF#1104  -  []  296.83 209.53 90 top
NOREF#1105  -  []  288.58 207.71 90 top
NOREF#1106  -  []  311.83 193.63 90 top
NOREF#1107  -  []  49.58 156.41 90 top
NOREF#1108  -  []  49.58 214.36 90 top
NOREF#1109  -  []  61.66 156.26 0 top
NOREF#1110  -  []  284.79 195.57 0 top
NOREF#1111  -  []  39.75 174.17 90 top
NOREF#1112  -  []  295.78 211.71 90 top
NOREF#1113  -  []  70.91 174.8 90 top
NOREF#1114  -  []  328.34 197.03 0 top
NOREF#1115  -  []  296.58 214.11 0 top
NOREF#1116  -  []  290.98 208.51 90 top
NOREF#1117  -  []  300.79 195.57 0 top
NOREF#1118  -  []  56 201.32 0 top
NOREF#1119  -  []  350.13 236.46 0 top
NOREF#1120  -  []  298.43 207.93 90 top
NOREF#1121  -  []  44.57 171.55 0 top
NOREF#1122  -  []  255.27 283.21 90 top
NOREF#1123  -  []  293.38 212.51 0 top
NOREF#1124  -  []  237.79 276.59 90 top
NOREF#1125  -  []  283.78 218.91 90 top
NOREF#1126  -  []  343.85 277.21 0 top
NOREF#1127  -  []  295.73 249.22 0 top
NOREF#1128  -  []  289.65 189.5 0 top
NOREF#1129  -  []  283.78 212.51 0 top
NOREF#1130  -  []  321.94 247.23 90 top
NOREF#1131  -  []  290.98 206.91 90 top
NOREF#1132  -  []  298.75 276.59 90 top
NOREF#1133  -  []  294.94 178.65 0 top
NOREF#1134  -  []  286.98 210.91 90 top
NOREF#1135  -  []  337.75 227.88 0 top
NOREF#1136  -  []  291.23 218.33 90 top
NOREF#1137  -  []  298.43 220.73 90 top
NOREF#1138  -  []  289.63 218.33 90 top
NOREF#1139  -  []  180.21 158.23 90 top
NOREF#1140  -  []  292.35 171.7 90 top
NOREF#1141  -  []  63.31 218.81 0 top
NOREF#1142  -  []  289.38 210.11 0 top
NOREF#1143  -  []  296.83 212.73 90 top
NOREF#1144  -  []  352.47 244.53 90 top
NOREF#1145  -  []  283.78 210.91 0 top
NOREF#1146  -  []  354.03 238.25 90 top
NOREF#1147  -  []  290.98 218.11 0 top
NOREF#1148  -  []  345.56 235.72 90 top
NOREF#1149  -  []  295.8 177.36 90 top
NOREF#1150  -  []  294.43 219.93 90 top
NOREF#1151  -  []  283.48 247.22 0 top
NOREF#1152  -  []  236.59 277.38 0 top
NOREF#1153  -  []  286.18 211.71 0 top
NOREF#1154  -  []  72.63 200.07 0 top
NOREF#1155  -  []  251.37 276.31 90 top
NOREF#1156  -  []  294.18 210.11 90 top
NOREF#1157  -  []  63.31 178 0 top
NOREF#1158  -  []  235.8 276.01 90 top
NOREF#1159  -  []  296.58 212.51 0 top
NOREF#1160  -  []  253.04 207.13 0 top
NOREF#1161  -  []  294.43 213.53 90 top
NOREF#1162  -  []  266.61 276.31 90 top
NOREF#1163  -  []  271.77 212.66 90 top
NOREF#1164  -  []  267.07 277.38 0 top
NOREF#1165  -  []  325.07 248.22 0 top
NOREF#1166  -  []  94.39 294.88 0 top
NOREF#1167  -  []  329.14 223.59 0 top
NOREF#1168  -  []  41.66 175.89 90 top
NOREF#1169  -  []  45.12 220.5 0 top
NOREF#1170  -  []  342.48 217.99 90 top
NOREF#1171  -  []  269.83 235.63 0 top
NOREF#1172  -  []  270.51 283.21 90 top
NOREF#1173  -  []  282.98 221.31 0 top
NOREF#1174  -  []  294.5 251.12 90 top
NOREF#1175  -  []  286.43 218.33 90 top
NOREF#1176  -  []  283.21 277.7 90 top
NOREF#1177  -  []  343.27 277.38 0 top
NOREF#1178  -  []  293.68 198.97 0 top
NOREF#1179  -  []  168.79 189.85 90 top
NOREF#1180  -  []  354.98 241.88 0 top
NOREF#1181  -  []  328.33 276.91 0 top
NOREF#1182  -  []  303.23 225.43 90 top
NOREF#1183  -  []  237.93 276.01 0 top
NOREF#1184  -  []  56.28 216.22 90 top
NOREF#1185  -  []  168.79 180.96 90 top
NOREF#1186  -  []  275.17 203.77 90 top
NOREF#1187  -  []  317.75 234.95 0 top
NOREF#1188  -  []  39.1 199.98 0 top
NOREF#1189  -  []  330.44 216.08 0 top
NOREF#1190  -  []  371.84 240.72 0 top
NOREF#1191  -  []  73.08 159.36 90 top
NOREF#1192  -  []  292.58 211.71 0 top
NOREF#1193  -  []  237.17 277.4 0 top
NOREF#1194  -  []  393.7 252.22 90 top
NOREF#1195  -  []  283.78 217.31 0 top
NOREF#1196  -  []  328.03 277.38 0 top
NOREF#1197  -  []  313.09 276.91 0 top
NOREF#1198  -  []  251.83 276.59 0 top
NOREF#1199  -  []  292.03 215.93 90 top
NOREF#1200  -  []  297.38 208.51 90 top
NOREF#1201  -  []  284.03 215.93 90 top
NOREF#1202  -  []  292.58 206.91 90 top
NOREF#1203  -  []  330.02 277.4 90 top
NOREF#1204  -  []  291.23 210.33 90 top
NOREF#1205  -  []  39.36 178.08 0 top
NOREF#1206  -  []  355.02 229.13 90 top
NOREF#1207  -  []  72.69 156.86 90 top
NOREF#1208  -  []  284.58 211.71 90 top
NOREF#1209  -  []  288.36 221.23 90 top
NOREF#1210  -  []  57.95 215.92 90 top
NOREF#1211  -  []  292.58 211.71 90 top
NOREF#1212  -  []  55.48 157.64 90 top
NOREF#1213  -  []  283.78 209.31 0 top
NOREF#1214  -  []  316.74 232.92 0 top
NOREF#1215  -  []  330.24 198.26 0 top
NOREF#1216  -  []  163.61 158.43 0 top
NOREF#1217  -  []  290.18 218.91 0 top
NOREF#1218  -  []  329.99 195.63 90 top
NOREF#1219  -  []  295.79 178.65 0 top
NOREF#1220  -  []  289.38 211.71 0 top
NOREF#1221  -  []  298.18 209.31 90 top
NOREF#1222  -  []  306.49 206.81 90 top
NOREF#1223  -  []  290.18 217.31 0 top
NOREF#1224  -  []  297.63 218.33 90 top
NOREF#1225  -  []  296.27 251.38 90 top
NOREF#1226  -  []  288.03 213.53 90 top
NOREF#1227  -  []  294.43 210.33 90 top
NOREF#1228  -  []  39.36 160.94 0 top
NOREF#1229  -  []  342.48 276.01 0 top
NOREF#1230  -  []  346.83 241.97 0 top
NOREF#1231  -  []  359.16 220.98 0 top
NOREF#1232  -  []  54.79 219.88 0 top
NOREF#1233  -  []  282.98 213.31 90 top
NOREF#1234  -  []  295.06 251.77 0 top
NOREF#1235  -  []  460.83 293.63 90 top
NOREF#1236  -  []  70.91 157.66 0 top
NOREF#1237  -  []  333.38 187.96 0 top
NOREF#1238  -  []  70.77 144.32 90 top
NOREF#1239  -  []  322.34 246.86 90 top
NOREF#1240  -  []  285.38 214.11 90 top
NOREF#1241  -  []  54.49 179.39 0 top
NOREF#1242  -  []  345.82 220.98 0 top
NOREF#1243  -  []  251.83 277.38 0 top
NOREF#1244  -  []  293.38 217.31 0 top
NOREF#1245  -  []  238.25 276.31 90 top
NOREF#1246  -  []  366.39 227.84 90 top
NOREF#1247  -  []  363.22 218.95 90 top
NOREF#1248  -  []  281.75 185.5 0 top
NOREF#1249  -  []  271.77 219.77 90 top
NOREF#1250  -  []  285.5 206.78 0 top
NOREF#1251  -  []  321.5 227.93 0 top
NOREF#1252  -  []  296.58 215.71 0 top
NOREF#1253  -  []  294.18 218.11 0 top
NOREF#1254  -  []  47.59 212.91 90 top
NOREF#1255  -  []  253.49 276.31 90 top
NOREF#1256  -  []  288.35 195.57 0 top
NOREF#1257  -  []  282.61 276.91 0 top
NOREF#1258  -  []  313.37 277.4 0 top
NOREF#1259  -  []  298.12 177.3 90 top
NOREF#1260  -  []  315.83 245.63 90 top
NOREF#1261  -  []  283.61 177.36 90 top
NOREF#1262  -  []  313.39 222.82 90 top
NOREF#1263  -  []  47.2 211.7 0 top
NOREF#1264  -  []  294.98 212.51 0 top
NOREF#1265  -  []  61.66 173.4 0 top
NOREF#1266  -  []  292.58 213.31 0 top
NOREF#1267  -  []  288.83 212.73 90 top
NOREF#1268  -  []  294.18 211.71 0 top
NOREF#1269  -  []  285.38 215.71 0 top
NOREF#1270  -  []  70.91 157.66 90 top
NOREF#1271  -  []  296.28 250.87 0 top
NOREF#1272  -  []  285.38 215.71 90 top
NOREF#1273  -  []  369.74 238.94 0 top
NOREF#1274  -  []  288.58 212.51 0 top
NOREF#1275  -  []  313.28 224.59 90 top
NOREF#1276  -  []  290.43 217.53 90 top
NOREF#1277  -  []  296.58 215.71 90 top
NOREF#1278  -  []  298.18 210.91 0 top
NOREF#1279  -  []  313.37 277.21 0 top
NOREF#1280  -  []  245.62 236.47 0 top
NOREF#1281  -  []  293.38 210.91 90 top
NOREF#1282  -  []  372.29 238.76 90 top
NOREF#1283  -  []  299.97 166.5 90 top
NOREF#1284  -  []  329.53 224.81 90 top
NOREF#1285  -  []  289.38 216.51 90 top
NOREF#1286  -  []  284.68 241.62 0 top
NOREF#1287  -  []  292.83 210.33 90 top
NOREF#1288  -  []  344.61 278.6 0 top
NOREF#1289  -  []  286.43 211.93 90 top
NOREF#1290  -  []  56.28 175.41 90 top
NOREF#1291  -  []  355.02 244.35 90 top
NOREF#1292  -  []  293.63 215.93 90 top
NOREF#1293  -  []  70.91 215.62 90 top
NOREF#1294  -  []  355.02 227.08 90 top
NOREF#1295  -  []  296.83 207.93 90 top
NOREF#1296  -  []  47.2 170.89 0 top
NOREF#1297  -  []  288.03 216.73 90 top
NOREF#1298  -  []  275.17 216.21 90 top
NOREF#1299  -  []  331.52 243.53 90 top
NOREF#1300  -  []  346.71 266.32 90 top
NOREF#1301  -  []  264.03 165.1 0 top
NOREF#1302  -  []  329.37 278.6 0 top
NOREF#1303  -  []  57.95 175.11 90 top
NOREF#1304  -  []  391.67 234.44 0 top
NOREF#1305  -  []  269.83 193.63 90 top
NOREF#1306  -  []  319.09 195.63 0 top
NOREF#1307  -  []  292.03 214.33 90 top
NOREF#1308  -  []  40.14 200.17 90 top
NOREF#1309  -  []  283.23 213.53 90 top
NOREF#1310  -  []  293.38 207.71 90 top
NOREF#1311  -  []  314.13 276.01 0 top
NOREF#1312  -  []  54.49 219.56 90 top
NOREF#1313  -  []  360.49 237.54 0 top
NOREF#1314  -  []  290.43 219.13 90 top
NOREF#1315  -  []  269.06 277.4 90 top
NOREF#1316  -  []  43.13 219.05 0 top
NOREF#1317  -  []  300.99 266.32 90 top
NOREF#1318  -  []  297.38 206.91 90 top
NOREF#1319  -  []  289.63 207.13 90 top
NOREF#1320  -  []  252.73 276.31 90 top
NOREF#1321  -  []  336.96 244.53 0 top
NOREF#1322  -  []  299.21 277.7 90 top
NOREF#1323  -  []  290.98 213.31 0 top
NOREF#1324  -  []  288.58 215.71 90 top
NOREF#1325  -  []  309.89 208.59 90 top
NOREF#1326  -  []  282.75 189.55 0 top
NOREF#1327  -  []  328.61 277.21 0 top
NOREF#1328  -  []  316.23 266.32 90 top
NOREF#1329  -  []  163.72 158.88 0 top
NOREF#1330  -  []  275.17 210.88 90 top
NOREF#1331  -  []  288.58 214.11 90 top
NOREF#1332  -  []  329.23 276.59 90 top
NOREF#1333  -  []  306.49 210.37 90 top
NOREF#1334  -  []  281.31 251.77 0 top
NOREF#1335  -  []  267.97 276.31 90 top
NOREF#1336  -  []  296.13 207.03 0 top
NOREF#1337  -  []  298.43 211.13 90 top
NOREF#1338  -  []  293.38 215.71 90 top
NOREF#1339  -  []  298.75 277.38 90 top
NOREF#1340  -  []  257.81 229.11 90 top
NOREF#1341  -  []  291.78 214.11 0 top
NOREF#1342  -  []  290.98 211.71 90 top
NOREF#1343  -  []  283.78 220.51 0 top
NOREF#1344  -  []  166.54 182.06 0 top
NOREF#1345  -  []  296.83 219.13 90 top
NOREF#1346  -  []  72.56 173.4 90 top
NOREF#1347  -  []  284.03 217.53 90 top
NOREF#1348  -  []  285.75 266.32 90 top
NOREF#1349  -  []  55.48 215.59 90 top
NOREF#1350  -  []  336.96 227.25 0 top
NOREF#1351  -  []  283.01 195.67 0 top
NOREF#1352  -  []  290.98 213.31 90 top
NOREF#1353  -  []  295.23 219.13 90 top
NOREF#1354  -  []  309.89 213.93 90 top
NOREF#1355  -  []  328.34 197.03 90 top
NOREF#1356  -  []  285.63 207.93 90 top
NOREF#1357  -  []  98.51 300.16 90 top
NOREF#1358  -  []  284.79 198.97 0 top
NOREF#1359  -  []  329.37 276.01 0 top
NOREF#1360  -  []  288.03 218.33 90 top
NOREF#1361  -  []  237.81 276.01 90 top
NOREF#1362  -  []  295.91 266.32 0 top
NOREF#1363  -  []  43.13 201.91 0 top
NOREF#1364  -  []  305.86 191.38 90 top
NOREF#1365  -  []  315.83 183.43 90 top
NOREF#1366  -  []  290.18 207.71 0 top
NOREF#1367  -  []  55.48 174.78 0 top
NOREF#1368  -  []  72.69 214.82 0 top
NOREF#1369  -  []  282.75 178.65 0 top
NOREF#1370  -  []  47.59 154.96 90 top
NOREF#1371  -  []  296.58 207.71 0 top
NOREF#1372  -  []  270.51 182.63 90 top
NOREF#1373  -  []  289.38 210.11 90 top
NOREF#1374  -  []  293.94 185.5 0 top
NOREF#1375  -  []  330.5 196.49 90 top
NOREF#1376  -  []  290.75 188.07 0 top
NOREF#1377  -  []  290.98 216.51 90 top
NOREF#1378  -  []  283.97 277.7 90 top
NOREF#1379  -  []  291.78 218.91 90 top
NOREF#1380  -  []  267.37 277.7 0 top
NOREF#1381  -  []  296.03 216.73 90 top
NOREF#1382  -  []  293.38 215.71 0 top
NOREF#1383  -  []  268.73 277.7 90 top
OSC1  OSC25M-S5032-AKER-15P  [OSC_3P2X5_4P_AKER]  291.85 186.8 90 bottom
OSC5  OSC100M-S2520-SITIME-1.8V  [OSC_2P5X2MM_6P_SIT9501]  56.98 217.19 270 bottom
OSC6  OSC100M-S2520-SITIME-1.8V  [OSC_2P5X2MM_6P_SIT9501]  56.98 200.05 270 bottom
OSC7  OSC100M-S2520-SITIME-1.8V  [OSC_2P5X2MM_6P_SIT9501]  56.98 159.24 270 bottom
OSC8  OSC100M-S2520-SITIME-1.8V  [OSC_2P5X2MM_6P_SIT9501]  56.98 176.38 270 bottom
PBGA23X23-M22X22-1-456  REF-CODE-SOCKET  [SOCKET_CODE]  60.45 267.72 0 top
R1  0-1-S8-YA  [R0805]  357.25 163.96 270 bottom
R2  0-1-S8-YA  [R0805]  359.54 163.96 270 bottom
R3  0-1-S8-YA  [R0805]  354.96 163.96 270 bottom
R4  NC/0-1-S8-YA  [R0805]  366.39 163.96 270 bottom
R5  NC/0-1-S8-YA  [R0805]  361.82 163.96 270 bottom
R6  NC/0-1-S8-YA  [R0805]  364.11 163.96 270 bottom
R7  NC/0-1-S8-YA  [R0805]  345.44 163.96 270 bottom
R8  0-1-S8-YA  [R0805]  334.01 163.96 270 bottom
R9  0-1-S8-YA  [R0805]  338.58 163.96 270 bottom
R10  NC/0-1-S8-YA  [R0805]  340.87 163.96 270 bottom
R11  NC/0-1-S8-YA  [R0805]  343.15 163.96 270 bottom
R12  0-1-S8-YA  [R0805]  336.3 163.96 270 bottom
R13  NC/0-1-S8-YA  [R0805]  398.02 232.66 0 bottom
R14  0-1-S8-YA  [R0805]  398.02 221.23 0 bottom
R15  0-1-S8-YA  [R0805]  398.02 223.52 0 bottom
R16  NC/0-1-S8-YA  [R0805]  398.02 230.38 0 bottom
R17  NC/0-1-S8-YA  [R0805]  398.02 234.95 0 bottom
R18  0-1-S8-YA  [R0805]  398.02 218.95 0 bottom
R19  0-1-S8-YA  [R0805]  398.02 245.36 0 bottom
R20  NC/0-1-S8-YA  [R0805]  398.02 252.22 0 bottom
R21  0-1-S8-YA  [R0805]  398.02 247.65 0 bottom
R22  NC/0-1-S8-YA  [R0805]  398.02 249.94 0 bottom
R23  NC/0-1-S8-YA  [R0805]  398.02 254.51 0 bottom
R24  0-1-S8-YA  [R0805]  398.02 243.08 0 bottom
R25  0-1-S8-YA  [R0805]  257.68 148.59 270 bottom
R26  NC/0-1-S8-YA  [R0805]  273.69 148.59 270 bottom
R27  0-1-S8-YA  [R0805]  262.25 148.59 270 bottom
R28  NC/0-1-S8-YA  [R0805]  269.11 148.59 270 bottom
R29  NC/0-1-S8-YA  [R0805]  271.4 148.59 270 bottom
R30  0-1-S8-YA  [R0805]  259.97 148.59 270 bottom
R31  0-1-S8-YA  [R0805]  242.19 148.59 270 bottom
R33  0-1-S8-YA  [R0805]  249.05 148.59 270 bottom
R34  NC/0-1-S8-YA  [R0805]  251.33 148.59 270 bottom
R36  0-1-S8-YA  [R0805]  244.47 148.59 270 bottom
R37  0-1-S8-YA  [R0805]  280.03 148.59 270 bottom
R38  NC/0-1-S8-YA  [R0805]  291.46 148.59 270 bottom
R39  0-1-S8-YA  [R0805]  282.32 148.59 270 bottom
R40  NC/0-1-S8-YA  [R0805]  286.89 148.59 270 bottom
R41  NC/0-1-S8-YA  [R0805]  289.18 148.59 270 bottom
R42  0-1-S8-YA  [R0805]  284.61 148.59 270 bottom
R43  0-1-S8-YA  [R0805]  313.56 148.59 270 bottom
R45  0-1-S8-YA  [R0805]  315.85 148.59 270 bottom
R46  NC/0-1-S8-YA  [R0805]  320.42 148.59 270 bottom
R48  0-1-S8-YA  [R0805]  318.13 148.59 270 bottom
R49  0-1-S8-YA  [R0805]  379.09 193.17 0 bottom
R51  0-1-S8-YA  [R0805]  379.09 195.45 0 bottom
R52  NC/0-1-S8-YA  [R0805]  379.09 200.03 0 bottom
R54  0-1-S8-YA  [R0805]  379.09 197.74 0 bottom
R55  0-1-S8-YA  [R0805]  296.54 148.59 270 bottom
R56  NC/0-1-S8-YA  [R0805]  307.97 148.59 270 bottom
R57  0-1-S8-YA  [R0805]  301.12 148.59 270 bottom
R58  NC/0-1-S8-YA  [R0805]  303.4 148.59 270 bottom
R59  NC/0-1-S8-YA  [R0805]  305.69 148.59 270 bottom
R60  0-1-S8-YA  [R0805]  298.83 148.59 270 bottom
R61  0-1-S8-YA  [R0805]  379.09 176.66 0 bottom
R62  NC/0-1-S8-YA  [R0805]  379.09 188.09 0 bottom
R63  0-1-S8-YA  [R0805]  379.09 178.94 0 bottom
R64  NC/0-1-S8-YA  [R0805]  379.09 183.51 0 bottom
R65  NC/0-1-S8-YA  [R0805]  379.09 185.8 0 bottom
R66  0-1-S8-YA  [R0805]  379.09 181.23 0 bottom
R67  NC/0-1-S8-YA  [R0805]  325.75 163.96 270 bottom
R68  0-1-S8-YA  [R0805]  314.32 163.96 270 bottom
R69  0-1-S8-YA  [R0805]  318.9 163.96 270 bottom
R70  NC/0-1-S8-YA  [R0805]  323.47 163.96 270 bottom
R71  NC/0-1-S8-YA  [R0805]  321.18 163.96 270 bottom
R72  0-1-S8-YA  [R0805]  316.61 163.96 270 bottom
R73  NC/0-1-S8-YA  [R0805]  222.44 228.73 180 bottom
R74  NC/0-1-S8-YA  [R0805]  222.44 203.58 180 bottom
R75  NC/0-1-S8-YA  [R0805]  222.44 217.3 180 bottom
R76  NC/0-1-S8-YA  [R0805]  222.44 226.44 180 bottom
R77  NC/0-1-S8-YA  [R0805]  222.44 208.15 180 bottom
R78  NC/0-1-S8-YA  [R0805]  222.44 205.87 180 bottom
R79  0-1-S8-YA  [R0805]  222.44 240.16 180 bottom
R80  0-1-S8-YA  [R0805]  222.44 237.87 180 bottom
R81  0-1-S8-YA  [R0805]  222.44 242.44 180 bottom
R100  33-1-S4-YA-V2  [R0402]  335.66 228.85 0 bottom
R101  33-1-S4-YA-V2  [R0402]  335.66 227.58 0 bottom
R102  33-1-S4-YA-V2  [R0402]  335.66 246.13 0 bottom
R103  33-1-S4-YA-V2  [R0402]  335.66 244.86 0 bottom
